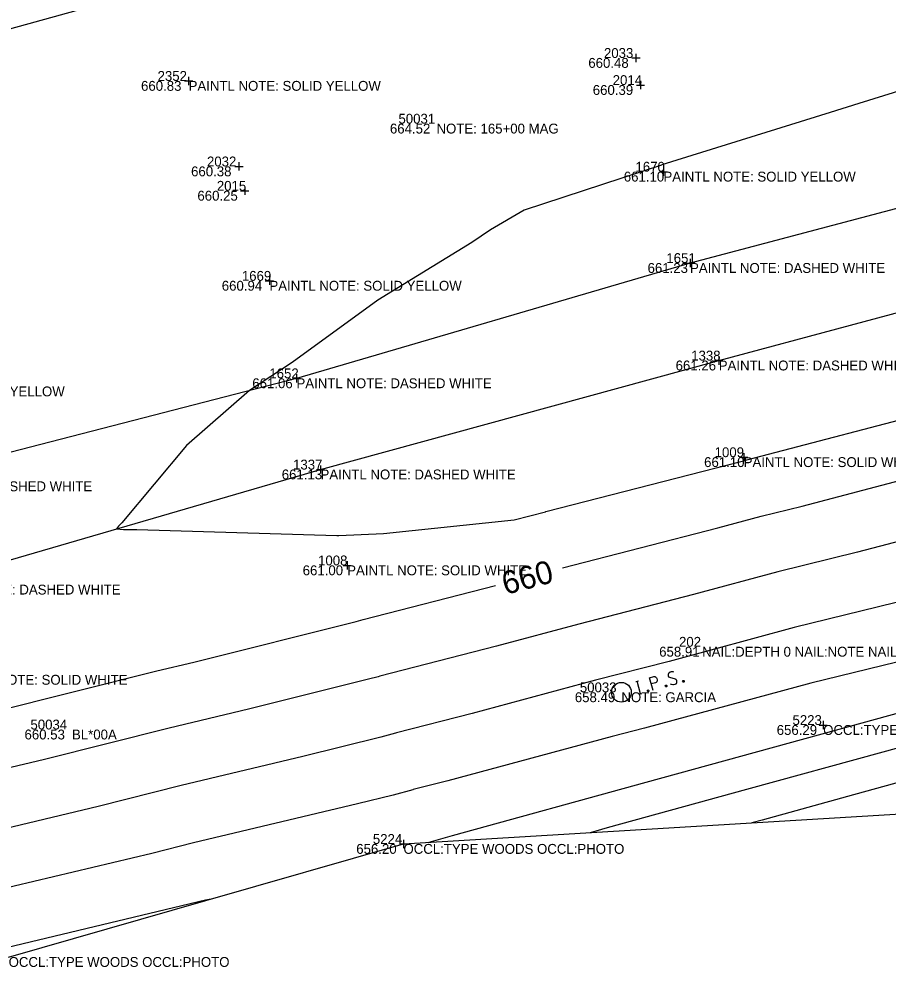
# Model space of a CAD drawing. Extents: x 2129350 to 2137777, y 657588 to 659885.
# Drawn here: x 2130064.8 to 2130170.4, y 657773.8 to 657889 of the extents above; entities that cross this region are included whole.
import ezdxf

# ---------------------------------------------------------------- set-up
doc = ezdxf.new("R2010")
doc.units = 0
for name, color, linetype in [('DT_X_Contour_Major', 7, 'Continuous'), ('DT_X_Contour_Minor', 7, 'Continuous'), ('DT_X_TIN_Hull', 7, 'Continuous'), ('PV_X_COP', 7, 'Continuous'), ('SV_P_Mon_Cells_Set', 7, 'Continuous'), ('SV_X_Shot_Marker', 7, 'Continuous'), ('SV_X_Text_Comment', 7, 'Continuous'), ('SV_X_Text_Elevation', 7, 'Continuous'), ('SV_X_Text_Name', 7, 'Continuous')]:
    doc.layers.add(name, color=color, linetype=linetype)

msp = doc.modelspace()

# ---------------------------------------------------------------- linework, layer by layer
at = {"layer": 'DT_X_Contour_Major'}
for points in [[(2130130.82, 657822.29), (2130149.71, 657827.15), (2130154.98, 657828.57), (2130159.95, 657829.8), (2130178.55, 657834.68), (2130188.88, 657835.07), (2130201.06, 657838.21), (2130201.11, 657838.23), (2130207.37, 657841.4), (2130224.46, 657845.77), (2130227.52, 657845.6)], [(2130025.67, 657796), (2130033.24, 657797.93), (2130036.88, 657798.58), (2130057.31, 657803.76), (2130061.34, 657804.72), (2130081.53, 657809.77), (2130086.05, 657810.85), (2130105.77, 657815.78), (2130106.34, 657815.93), (2130106.61, 657816), (2130122.71, 657820.14)], [(2130172.54, 657800.67), (2130169.77, 657799.91), (2130153.21, 657795.35), (2130136.27, 657790.68), (2130134.21, 657790.11)]]:
    msp.add_lwpolyline(points, dxfattribs=at)
at = {"layer": 'DT_X_Contour_Minor'}
for points in [[(2130185.47, 657884.52), (2130166.85, 657878.72), (2130163.37, 657877.61), (2130142.92, 657871.26), (2130142.88, 657871.24), (2130126.17, 657865.74), (2130122.1, 657863.37), (2130119.83, 657861.84), (2130108.41, 657854.8), (2130097.97, 657847.25), (2130092.79, 657843.84), (2130085.14, 657837.14), (2130077.28, 657827.77), (2130076.88, 657827.35), (2130076.65, 657827.02), (2130077.48, 657826.97), (2130079.11, 657826.94), (2130103.41, 657826.21), (2130103.65, 657826.21), (2130103.66, 657826.21), (2130109.1, 657826.47), (2130124.97, 657828.13), (2130128.76, 657829.11), (2130128.8, 657829.12), (2130152.68, 657835.26), (2130152.97, 657835.34), (2130153.24, 657835.41), (2130177.1, 657841.67)], [(2130180.01, 657827.69), (2130166.66, 657824.18), (2130156.98, 657821.81), (2130146.74, 657819.04), (2130132.82, 657815.46), (2130122.82, 657812.76), (2130108.64, 657809.11), (2130108.44, 657809.06), (2130107.26, 657808.75), (2130092.67, 657805.1), (2130083.02, 657802.8), (2130067.87, 657799.01), (2130058.81, 657796.86)], [(2130173.36, 657818.57), (2130158.99, 657815.04), (2130143.78, 657810.93), (2130134.84, 657808.63), (2130119.86, 657804.59), (2130110.67, 657802.23), (2130110.54, 657802.2), (2130108.75, 657801.71), (2130099.29, 657799.35), (2130084.5, 657795.83), (2130074.4, 657793.3), (2130060.3, 657789.95)], [(2130202.99, 657789.04), (2130215.23, 657793.38), (2130217.77, 657793.17), (2130214.09, 657799.18), (2130227.46, 657807.15), (2130230.54, 657807.91), (2130218.29, 657816.9), (2130207.92, 657814.78), (2130206.09, 657814.59), (2130186.67, 657809.12), (2130189.75, 657807.96), (2130183.84, 657808), (2130163.95, 657802.54), (2130140.96, 657796.2), (2130117.43, 657789.72), (2130114.57, 657788.93)], [(2130180.07, 657812.95), (2130161, 657808.27), (2130140.81, 657802.82), (2130136.85, 657801.8), (2130116.89, 657796.42), (2130112.7, 657795.34), (2130112.64, 657795.33), (2130110.25, 657794.68), (2130105.92, 657793.6), (2130085.99, 657788.86), (2130080.92, 657787.6), (2130061.79, 657783.04)], [(2130192.76, 657791.35), (2130210.77, 657797.74), (2130212.16, 657797.62), (2130208.4, 657803.76), (2130209.28, 657805.14), (2130212.62, 657805.97), (2130210.64, 657807.42), (2130208.97, 657807.08), (2130201.77, 657806.34), (2130199.58, 657805.72), (2130201.16, 657805.13), (2130202.35, 657803.94), (2130194.03, 657799.62), (2130184.34, 657799.7), (2130175.58, 657797.29), (2130165.46, 657794.5), (2130155.11, 657791.65), (2130153.85, 657791.3)], [(2130088.16, 657782.05), (2130087.47, 657781.89), (2130087.45, 657781.89), (2130063.29, 657776.13)]]:
    msp.add_lwpolyline(points, dxfattribs=at)
at = {"layer": 'DT_X_TIN_Hull'}
msp.add_lwpolyline([(2130063.53, 657775), (2130087.48, 657781.86), (2130111.51, 657788.74), (2130184.72, 657793.16), (2130224.7, 657784.14), (2130227.31, 657786.04), (2130260.53, 657795.45), (2130300.78, 657808.51), (2130376.54, 657844.16), (2130411.67, 657845.04), (2130416.24, 657846.18), (2130500.88, 657865.38), (2130572.37, 657881.8), (2130602.46, 657888.27), (2130637.43, 657896.31), (2130707.51, 657930.94), (2130731.78, 657936.94), (2130795.64, 657946.55)], dxfattribs=at)
at = {"layer": 'PV_X_COP'}
for points in [[(2130037.09, 657880.45), (2130085.21, 657893.8), (2130133.36, 657906.99), (2130181.98, 657920.22), (2130229.94, 657933.91), (2130277.86, 657946.56), (2130326.08, 657959.87), (2130374.09, 657973.32), (2130422.71, 657986.65), (2130470.82, 658000.08), (2130519.45, 658012.91), (2130567.41, 658026.23), (2130615.61, 658039.6), (2130663.49, 658052.2), (2130712.28, 658065.72), (2130760.53, 658079.19)], [(2130773.41, 658031.03), (2130725.14, 658018.16), (2130677.1, 658004.43), (2130628.66, 657991.98), (2130580.31, 657978.68), (2130532.19, 657965.06), (2130483.96, 657951.76), (2130435.47, 657938.65), (2130387.69, 657925.25), (2130339.28, 657912.11), (2130291.38, 657898.77), (2130243.11, 657885.29), (2130194.87, 657872.16), (2130146.33, 657859.33), (2130098.51, 657845.32), (2130049.97, 657832.8)], [(2130053.42, 657820.25), (2130101.43, 657834.24), (2130149.82, 657847.48), (2130197.82, 657860.36), (2130245.91, 657874.04), (2130294.49, 657887.16), (2130342.81, 657900.65), (2130391.01, 657913.42), (2130438.97, 657926.55), (2130486.95, 657939.82), (2130535.36, 657953.68), (2130583.74, 657966.83), (2130631.76, 657979.83), (2130680.29, 657993.15), (2130728.05, 658006.58), (2130776.44, 658019.66)]]:
    msp.add_lwpolyline(points, dxfattribs=at)
at = {"layer": 'SV_P_Mon_Cells_Set'}
for points in [[(2130141.83, 657807.39), (2130141.41, 657808.94), (2130141.92, 657809.08), (2130141.98, 657809.08), (2130142.06, 657809.07), (2130142.1, 657809.06), (2130142.14, 657809.04), (2130142.19, 657808.99), (2130142.24, 657808.94), (2130142.29, 657808.85), (2130142.33, 657808.7), (2130142.33, 657808.65), (2130142.33, 657808.57), (2130142.31, 657808.48), (2130142.28, 657808.43), (2130142.26, 657808.4), (2130142.21, 657808.36), (2130142.13, 657808.32), (2130141.62, 657808.18)], [(2130144.34, 657809.62), (2130144.32, 657809.64), (2130144.28, 657809.65), (2130144.17, 657809.66), (2130144.05, 657809.66), (2130143.96, 657809.63), (2130143.93, 657809.62), (2130143.8, 657809.55), (2130143.71, 657809.45), (2130143.66, 657809.33), (2130143.66, 657809.23), (2130143.68, 657809.15), (2130143.73, 657809.06), (2130143.84, 657809), (2130144.52, 657808.79), (2130144.59, 657808.76), (2130144.62, 657808.72), (2130144.67, 657808.65), (2130144.69, 657808.58), (2130144.69, 657808.5), (2130144.7, 657808.45), (2130144.69, 657808.38), (2130144.68, 657808.33), (2130144.67, 657808.29), (2130144.65, 657808.24), (2130144.63, 657808.21), (2130144.59, 657808.17), (2130144.56, 657808.15), (2130144.47, 657808.11), (2130144.32, 657808.07), (2130144.22, 657808.07), (2130144.06, 657808.12), (2130143.95, 657808.17)], [(2130139.73, 657808.48), (2130140.07, 657808.57)], [(2130140.32, 657806.98), (2130139.9, 657808.52)], [(2130143.36, 657808.03), (2130143.41, 657808.05), (2130143.45, 657808.03), (2130143.5, 657807.99), (2130143.51, 657807.93), (2130143.5, 657807.87), (2130143.47, 657807.84), (2130143.42, 657807.83), (2130143.38, 657807.84), (2130143.33, 657807.88), (2130143.32, 657807.94), (2130143.33, 657808), (2130143.36, 657808.03)], [(2130145.47, 657808.61), (2130145.52, 657808.62), (2130145.56, 657808.61), (2130145.6, 657808.57), (2130145.62, 657808.51), (2130145.6, 657808.45), (2130145.58, 657808.42), (2130145.52, 657808.4), (2130145.48, 657808.42), (2130145.44, 657808.46), (2130145.42, 657808.52), (2130145.44, 657808.57), (2130145.47, 657808.61)], [(2130140.15, 657806.93), (2130140.49, 657807.03)], [(2130141.19, 657807.44), (2130141.24, 657807.45), (2130141.28, 657807.44), (2130141.33, 657807.4), (2130141.34, 657807.34), (2130141.33, 657807.28), (2130141.3, 657807.25), (2130141.25, 657807.23), (2130141.21, 657807.25), (2130141.16, 657807.29), (2130141.15, 657807.35), (2130141.17, 657807.41), (2130141.19, 657807.44)]]:
    msp.add_lwpolyline(points, dxfattribs=at)
msp.add_circle((2130137.99, 657807.17), 1.2, dxfattribs=at)
at = {"layer": 'SV_X_Shot_Marker'}
for p, q in [((2130139.26, 657884.25), (2130140.26, 657884.25)), ((2130139.76, 657884.75), (2130139.76, 657883.75)), ((2130139.76, 657884.25), (2130139.76, 657884.25)), ((2130085.4, 657881.96), (2130085.4, 657880.96)), ((2130084.9, 657881.46), (2130085.9, 657881.46)), ((2130085.4, 657881.46), (2130085.4, 657881.46)), ((2130139.81, 657880.96), (2130140.81, 657880.96)), ((2130140.31, 657881.46), (2130140.31, 657880.46)), ((2130140.31, 657880.96), (2130140.31, 657880.96)), ((2130091.51, 657871.57), (2130091.51, 657870.57)), ((2130091.01, 657871.07), (2130092.01, 657871.07)), ((2130091.51, 657871.07), (2130091.51, 657871.07)), ((2130142.6, 657870.43), (2130143.6, 657870.43)), ((2130143.1, 657870.93), (2130143.1, 657869.93)), ((2130143.1, 657870.43), (2130143.1, 657870.43)), ((2130091.72, 657868.11), (2130092.72, 657868.11)), ((2130092.22, 657868.61), (2130092.22, 657867.61)), ((2130092.22, 657868.11), (2130092.22, 657868.11)), ((2130146.33, 657859.83), (2130146.33, 657858.83)), ((2130145.83, 657859.33), (2130146.83, 657859.33)), ((2130146.33, 657859.33), (2130146.33, 657859.33)), ((2130095.22, 657857.67), (2130095.22, 657856.67)), ((2130094.72, 657857.17), (2130095.72, 657857.17)), ((2130095.22, 657857.17), (2130095.22, 657857.17)), ((2130149.32, 657847.48), (2130150.32, 657847.48)), ((2130149.82, 657847.98), (2130149.82, 657846.98)), ((2130149.82, 657847.48), (2130149.82, 657847.48)), ((2130098.01, 657845.32), (2130099.01, 657845.32)), ((2130098.51, 657845.82), (2130098.51, 657844.82)), ((2130098.51, 657845.32), (2130098.51, 657845.32)), ((2130152.35, 657835.74), (2130153.35, 657835.74)), ((2130152.85, 657836.24), (2130152.85, 657835.24)), ((2130152.85, 657835.74), (2130152.85, 657835.74)), ((2130101.43, 657834.74), (2130101.43, 657833.74)), ((2130100.93, 657834.24), (2130101.93, 657834.24)), ((2130101.43, 657834.24), (2130101.43, 657834.24)), ((2130104.67, 657823.09), (2130104.67, 657822.09)), ((2130104.17, 657822.59), (2130105.17, 657822.59)), ((2130104.67, 657822.59), (2130104.67, 657822.59)), ((2130162.51, 657803.69), (2130162.51, 657802.69)), ((2130162.01, 657803.19), (2130163.01, 657803.19)), ((2130162.51, 657803.19), (2130162.51, 657803.19)), ((2130111.01, 657788.74), (2130112.01, 657788.74)), ((2130111.51, 657789.24), (2130111.51, 657788.24)), ((2130111.51, 657788.74), (2130111.51, 657788.74))]:
    msp.add_line(p, q, dxfattribs=at)

# ---------------------------------------------------------------- texts
at = {"layer": 'DT_X_Contour_Major'}
msp.add_text('660', height=2.8, rotation=14.8427, dxfattribs=at).set_placement((2130123.89, 657818.99))
at = {"layer": 'SV_X_Text_Comment'}
for s, p in [('PAINTL NOTE: SOLID YELLOW', (2130085.4, 657880.26)), ('NOTE: 165+00 MAG', (2130115.52, 657875.07)), ('PAINTL NOTE: SOLID YELLOW', (2130143.1, 657869.23)), ('PAINTL NOTE: DASHED WHITE', (2130146.33, 657858.13)), ('PAINTL NOTE: SOLID YELLOW', (2130095.22, 657855.97)), ('PAINTL NOTE: DASHED WHITE', (2130149.82, 657846.28)), ('PAINTL NOTE: DASHED WHITE', (2130098.51, 657844.12)), ('PAINTL NOTE: SOLID YELLOW', (2130046.98, 657843.13)), ('PAINTL NOTE: SOLID WHITE', (2130152.85, 657834.54)), ('PAINTL NOTE: DASHED WHITE', (2130101.43, 657833.04)), ('PAINTL NOTE: DASHED WHITE', (2130049.97, 657831.6)), ('PAINTL NOTE: SOLID WHITE', (2130104.67, 657821.39)), ('PAINTL NOTE: DASHED WHITE', (2130053.42, 657819.05)), ('NAIL:DEPTH 0 NAIL:NOTE NAIL:PHOTO', (2130147.8, 657811.5)), ('PAINTL NOTE: SOLID WHITE', (2130056.12, 657808.09)), ('NOTE: GARCIA', (2130137.99, 657805.97)), ('BL*00A', (2130071.23, 657801.44)), ('OCCL:TYPE WOODS OCCL:PHOTO', (2130162.51, 657801.99)), ('OCCL:TYPE WOODS OCCL:PHOTO', (2130111.51, 657787.54)), ('OCCL:TYPE WOODS OCCL:PHOTO', (2130063.53, 657773.8))]:
    msp.add_text(s, height=1.2, dxfattribs=at).set_placement(p)
at = {"layer": 'SV_X_Text_Elevation'}
for s, p in [('660.48', (2130133.97, 657883.05)), ('660.83', (2130079.62, 657880.26)), ('660.39', (2130134.51, 657879.76)), ('664.52', (2130109.86, 657875.07)), ('660.38', (2130085.7, 657869.87)), ('661.10', (2130138.28, 657869.23)), ('660.25', (2130086.47, 657866.91)), ('661.23', (2130141.17, 657858.13)), ('660.94', (2130089.43, 657855.97)), ('661.26', (2130144.58, 657846.28)), ('661.06', (2130093.14, 657844.12)), ('661.10', (2130148.04, 657834.54)), ('661.13', (2130096.72, 657833.04)), ('661.00', (2130099.26, 657821.39)), ('658.91', (2130142.58, 657811.5)), ('658.49', (2130132.33, 657805.97)), ('660.53', (2130065.46, 657801.44)), ('656.29', (2130156.86, 657801.99)), ('656.20', (2130105.77, 657787.54))]:
    msp.add_text(s, height=1.2, dxfattribs=at).set_placement(p)
at = {"layer": 'SV_X_Text_Name'}
for s, p in [('2033', (2130135.87, 657884.25)), ('2352', (2130081.63, 657881.46)), ('2014', (2130136.93, 657880.96)), ('50031', (2130110.9, 657876.27)), ('2032', (2130087.63, 657871.07)), ('1670', (2130139.7, 657870.43)), ('2015', (2130088.83, 657868.11)), ('1651', (2130143.45, 657859.33)), ('1669', (2130091.87, 657857.17)), ('1338', (2130146.47, 657847.48)), ('1652', (2130095.21, 657845.32)), ('1009', (2130149.32, 657835.74)), ('1337', (2130098.09, 657834.24)), ('1008', (2130101.13, 657822.59)), ('202', (2130144.99, 657812.7)), ('50033', (2130132.94, 657807.17)), ('50034', (2130066.18, 657802.65)), ('5223', (2130158.78, 657803.19)), ('5224', (2130107.79, 657788.74))]:
    msp.add_text(s, height=1.2, dxfattribs=at).set_placement(p)

doc.saveas('drawing.dxf')
